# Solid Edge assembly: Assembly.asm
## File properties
Author: Administrator
Template: Normal.asm
Last saved by: Rajat Kamboj
Revision: 25
Application: Solid Edge
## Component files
Stock_support_base.par
thrust_bearing.par
adjusting_screw_nut.par
support_adjusting_screw.par
support_roller_bracket.par
stock_support_roller.par
adjusting_nut_handle.par
adjusting_screw_guide.par
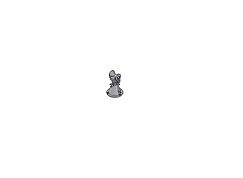
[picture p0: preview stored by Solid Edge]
